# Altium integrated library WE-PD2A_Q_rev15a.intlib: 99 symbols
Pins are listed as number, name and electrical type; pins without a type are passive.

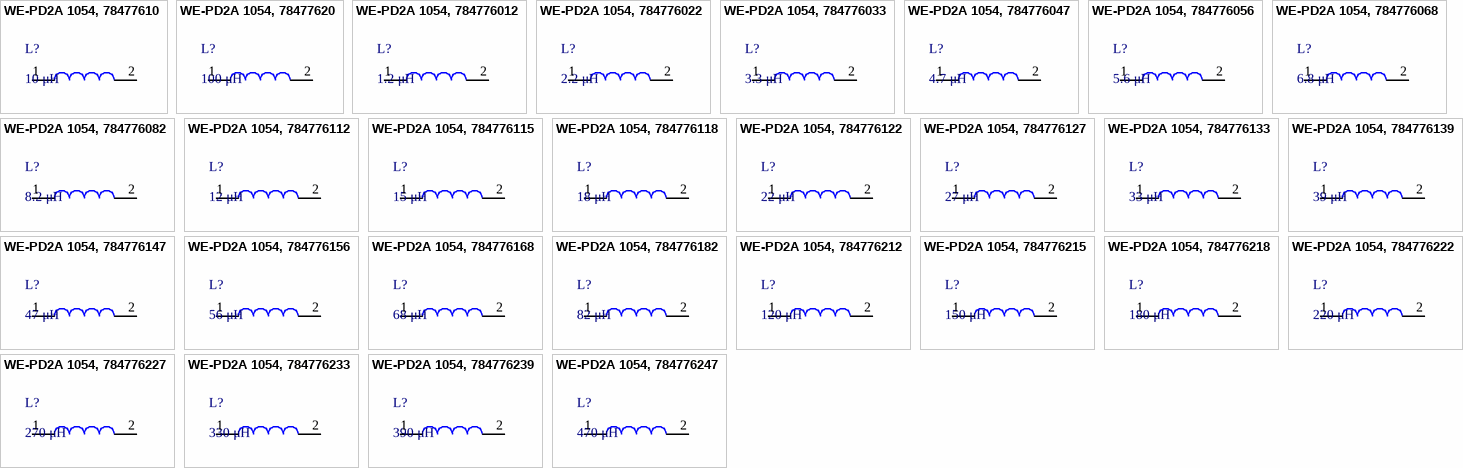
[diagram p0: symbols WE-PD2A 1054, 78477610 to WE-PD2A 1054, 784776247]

## WE-PD2A 1054, 78477610
designator L?, comment 10 μH
WE-PD2A SMD Power Inductor, Inductance = 10 μH; partNo: 78477610; Manufacturer: Wurth Elektronik
footprint WE-PD2A_1054
pins: 1, 2

## WE-PD2A 1054, 78477620
designator L?, comment 100 μH
WE-PD2A SMD Power Inductor, Inductance = 100 μH; partNo: 78477620; Manufacturer: Wurth Elektronik
footprint WE-PD2A_1054
pins: 1, 2

## WE-PD2A 1054, 784776012
designator L?, comment 1.2 μH
WE-PD2A SMD Power Inductor, Inductance = 1.2 μH; partNo: 784776012; Manufacturer: Wurth Elektronik
footprint WE-PD2A_1054
pins: 1, 2

## WE-PD2A 1054, 784776022
designator L?, comment 2.2 μH
WE-PD2A SMD Power Inductor, Inductance = 2.2 μH; partNo: 784776022; Manufacturer: Wurth Elektronik
footprint WE-PD2A_1054
pins: 1, 2

## WE-PD2A 1054, 784776033
designator L?, comment 3.3 μH
WE-PD2A SMD Power Inductor, Inductance = 3.3 μH; partNo: 784776033; Manufacturer: Wurth Elektronik
footprint WE-PD2A_1054
pins: 1, 2

## WE-PD2A 1054, 784776047
designator L?, comment 4.7 μH
WE-PD2A SMD Power Inductor, Inductance = 4.7 μH; partNo: 784776047; Manufacturer: Wurth Elektronik
footprint WE-PD2A_1054
pins: 1, 2

## WE-PD2A 1054, 784776056
designator L?, comment 5.6 μH
WE-PD2A SMD Power Inductor, Inductance = 5.6 μH; partNo: 784776056; Manufacturer: Wurth Elektronik
footprint WE-PD2A_1054
pins: 1, 2

## WE-PD2A 1054, 784776068
designator L?, comment 6.8 μH
WE-PD2A SMD Power Inductor, Inductance = 6.8 μH; partNo: 784776068; Manufacturer: Wurth Elektronik
footprint WE-PD2A_1054
pins: 1, 2

## WE-PD2A 1054, 784776082
designator L?, comment 8.2 μH
WE-PD2A SMD Power Inductor, Inductance = 8.2 μH; partNo: 784776082; Manufacturer: Wurth Elektronik
footprint WE-PD2A_1054
pins: 1, 2

## WE-PD2A 1054, 784776112
designator L?, comment 12 μH
WE-PD2A SMD Power Inductor, Inductance = 12 μH; partNo: 784776112; Manufacturer: Wurth Elektronik
footprint WE-PD2A_1054
pins: 1, 2

## WE-PD2A 1054, 784776115
designator L?, comment 15 μH
WE-PD2A SMD Power Inductor, Inductance = 15 μH; partNo: 784776115; Manufacturer: Wurth Elektronik
footprint WE-PD2A_1054
pins: 1, 2

## WE-PD2A 1054, 784776118
designator L?, comment 18 μH
WE-PD2A SMD Power Inductor, Inductance = 18 μH; partNo: 784776118; Manufacturer: Wurth Elektronik
footprint WE-PD2A_1054
pins: 1, 2

## WE-PD2A 1054, 784776122
designator L?, comment 22 μH
WE-PD2A SMD Power Inductor, Inductance = 22 μH; partNo: 784776122; Manufacturer: Wurth Elektronik
footprint WE-PD2A_1054
pins: 1, 2

## WE-PD2A 1054, 784776127
designator L?, comment 27 μH
WE-PD2A SMD Power Inductor, Inductance = 27 μH; partNo: 784776127; Manufacturer: Wurth Elektronik
footprint WE-PD2A_1054
pins: 1, 2

## WE-PD2A 1054, 784776133
designator L?, comment 33 μH
WE-PD2A SMD Power Inductor, Inductance = 33 μH; partNo: 784776133; Manufacturer: Wurth Elektronik
footprint WE-PD2A_1054
pins: 1, 2

## WE-PD2A 1054, 784776139
designator L?, comment 39 μH
WE-PD2A SMD Power Inductor, Inductance = 39 μH; partNo: 784776139; Manufacturer: Wurth Elektronik
footprint WE-PD2A_1054
pins: 1, 2

## WE-PD2A 1054, 784776147
designator L?, comment 47 μH
WE-PD2A SMD Power Inductor, Inductance = 47 μH; partNo: 784776147; Manufacturer: Wurth Elektronik
footprint WE-PD2A_1054
pins: 1, 2

## WE-PD2A 1054, 784776156
designator L?, comment 56 μH
WE-PD2A SMD Power Inductor, Inductance = 56 μH; partNo: 784776156; Manufacturer: Wurth Elektronik
footprint WE-PD2A_1054
pins: 1, 2

## WE-PD2A 1054, 784776168
designator L?, comment 68 μH
WE-PD2A SMD Power Inductor, Inductance = 68 μH; partNo: 784776168; Manufacturer: Wurth Elektronik
footprint WE-PD2A_1054
pins: 1, 2

## WE-PD2A 1054, 784776182
designator L?, comment 82 μH
WE-PD2A SMD Power Inductor, Inductance = 82 μH; partNo: 784776182; Manufacturer: Wurth Elektronik
footprint WE-PD2A_1054
pins: 1, 2

## WE-PD2A 1054, 784776212
designator L?, comment 120 μH
WE-PD2A SMD Power Inductor, Inductance = 120 μH; partNo: 784776212; Manufacturer: Wurth Elektronik
footprint WE-PD2A_1054
pins: 1, 2

## WE-PD2A 1054, 784776215
designator L?, comment 150 μH
WE-PD2A SMD Power Inductor, Inductance = 150 μH; partNo: 784776215; Manufacturer: Wurth Elektronik
footprint WE-PD2A_1054
pins: 1, 2

## WE-PD2A 1054, 784776218
designator L?, comment 180 μH
WE-PD2A SMD Power Inductor, Inductance = 180 μH; partNo: 784776218; Manufacturer: Wurth Elektronik
footprint WE-PD2A_1054
pins: 1, 2

## WE-PD2A 1054, 784776222
designator L?, comment 220 μH
WE-PD2A SMD Power Inductor, Inductance = 220 μH; partNo: 784776222; Manufacturer: Wurth Elektronik
footprint WE-PD2A_1054
pins: 1, 2

## WE-PD2A 1054, 784776227
designator L?, comment 270 μH
WE-PD2A SMD Power Inductor, Inductance = 270 μH; partNo: 784776227; Manufacturer: Wurth Elektronik
footprint WE-PD2A_1054
pins: 1, 2

## WE-PD2A 1054, 784776233
designator L?, comment 330 μH
WE-PD2A SMD Power Inductor, Inductance = 330 μH; partNo: 784776233; Manufacturer: Wurth Elektronik
footprint WE-PD2A_1054
pins: 1, 2

## WE-PD2A 1054, 784776239
designator L?, comment 390 μH
WE-PD2A SMD Power Inductor, Inductance = 390 μH; partNo: 784776239; Manufacturer: Wurth Elektronik
footprint WE-PD2A_1054
pins: 1, 2

## WE-PD2A 1054, 784776247
designator L?, comment 470 μH
WE-PD2A SMD Power Inductor, Inductance = 470 μH; partNo: 784776247; Manufacturer: Wurth Elektronik
footprint WE-PD2A_1054
pins: 1, 2


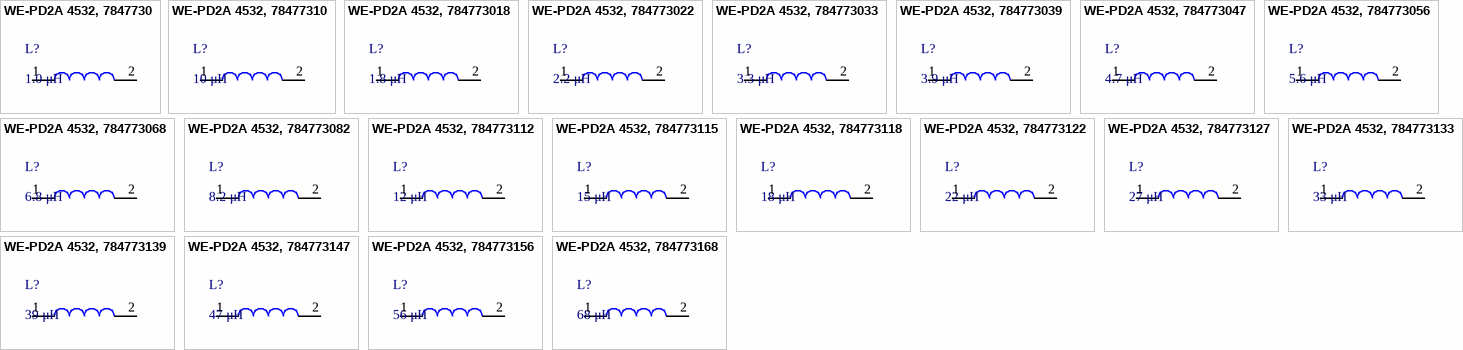
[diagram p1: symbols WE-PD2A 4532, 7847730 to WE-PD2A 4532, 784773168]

## WE-PD2A 4532, 7847730
designator L?, comment 1.0 μH
WE-PD2A SMD Power Inductor, Inductance = 1.0 μH; partNo: 7847730; Manufacturer: Wurth Elektronik
footprint WE-PD2A_4532
pins: 1, 2

## WE-PD2A 4532, 78477310
designator L?, comment 10 μH
WE-PD2A SMD Power Inductor, Inductance = 10 μH; partNo: 78477310; Manufacturer: Wurth Elektronik
footprint WE-PD2A_4532
pins: 1, 2

## WE-PD2A 4532, 784773018
designator L?, comment 1.8 μH
WE-PD2A SMD Power Inductor, Inductance = 1.8 μH; partNo: 784773018; Manufacturer: Wurth Elektronik
footprint WE-PD2A_4532
pins: 1, 2

## WE-PD2A 4532, 784773022
designator L?, comment 2.2 μH
WE-PD2A SMD Power Inductor, Inductance = 2.2 μH; partNo: 784773022; Manufacturer: Wurth Elektronik
footprint WE-PD2A_4532
pins: 1, 2

## WE-PD2A 4532, 784773033
designator L?, comment 3.3 μH
WE-PD2A SMD Power Inductor, Inductance = 3.3 μH; partNo: 784773033; Manufacturer: Wurth Elektronik
footprint WE-PD2A_4532
pins: 1, 2

## WE-PD2A 4532, 784773039
designator L?, comment 3.9 μH
WE-PD2A SMD Power Inductor, Inductance = 3.9 μH; partNo: 784773039; Manufacturer: Wurth Elektronik
footprint WE-PD2A_4532
pins: 1, 2

## WE-PD2A 4532, 784773047
designator L?, comment 4.7 μH
WE-PD2A SMD Power Inductor, Inductance = 4.7 μH; partNo: 784773047; Manufacturer: Wurth Elektronik
footprint WE-PD2A_4532
pins: 1, 2

## WE-PD2A 4532, 784773056
designator L?, comment 5.6 μH
WE-PD2A SMD Power Inductor, Inductance = 5.6 μH; partNo: 784773056; Manufacturer: Wurth Elektronik
footprint WE-PD2A_4532
pins: 1, 2

## WE-PD2A 4532, 784773068
designator L?, comment 6.8 μH
WE-PD2A SMD Power Inductor, Inductance = 6.8 μH; partNo: 784773068; Manufacturer: Wurth Elektronik
footprint WE-PD2A_4532
pins: 1, 2

## WE-PD2A 4532, 784773082
designator L?, comment 8.2 μH
WE-PD2A SMD Power Inductor, Inductance = 8.2 μH; partNo: 784773082; Manufacturer: Wurth Elektronik
footprint WE-PD2A_4532
pins: 1, 2

## WE-PD2A 4532, 784773112
designator L?, comment 12 μH
WE-PD2A SMD Power Inductor, Inductance = 12 μH; partNo: 784773112; Manufacturer: Wurth Elektronik
footprint WE-PD2A_4532
pins: 1, 2

## WE-PD2A 4532, 784773115
designator L?, comment 15 μH
WE-PD2A SMD Power Inductor, Inductance = 15 μH; partNo: 784773115; Manufacturer: Wurth Elektronik
footprint WE-PD2A_4532
pins: 1, 2

## WE-PD2A 4532, 784773118
designator L?, comment 18 μH
WE-PD2A SMD Power Inductor, Inductance = 18 μH; partNo: 784773118; Manufacturer: Wurth Elektronik
footprint WE-PD2A_4532
pins: 1, 2

## WE-PD2A 4532, 784773122
designator L?, comment 22 μH
WE-PD2A SMD Power Inductor, Inductance = 22 μH; partNo: 784773122; Manufacturer: Wurth Elektronik
footprint WE-PD2A_4532
pins: 1, 2

## WE-PD2A 4532, 784773127
designator L?, comment 27 μH
WE-PD2A SMD Power Inductor, Inductance = 27 μH; partNo: 784773127; Manufacturer: Wurth Elektronik
footprint WE-PD2A_4532
pins: 1, 2

## WE-PD2A 4532, 784773133
designator L?, comment 33 μH
WE-PD2A SMD Power Inductor, Inductance = 33 μH; partNo: 784773133; Manufacturer: Wurth Elektronik
footprint WE-PD2A_4532
pins: 1, 2

## WE-PD2A 4532, 784773139
designator L?, comment 39 μH
WE-PD2A SMD Power Inductor, Inductance = 39 μH; partNo: 784773139; Manufacturer: Wurth Elektronik
footprint WE-PD2A_4532
pins: 1, 2

## WE-PD2A 4532, 784773147
designator L?, comment 47 μH
WE-PD2A SMD Power Inductor, Inductance = 47 μH; partNo: 784773147; Manufacturer: Wurth Elektronik
footprint WE-PD2A_4532
pins: 1, 2

## WE-PD2A 4532, 784773156
designator L?, comment 56 μH
WE-PD2A SMD Power Inductor, Inductance = 56 μH; partNo: 784773156; Manufacturer: Wurth Elektronik
footprint WE-PD2A_4532
pins: 1, 2

## WE-PD2A 4532, 784773168
designator L?, comment 68 μH
WE-PD2A SMD Power Inductor, Inductance = 68 μH; partNo: 784773168; Manufacturer: Wurth Elektronik
footprint WE-PD2A_4532
pins: 1, 2


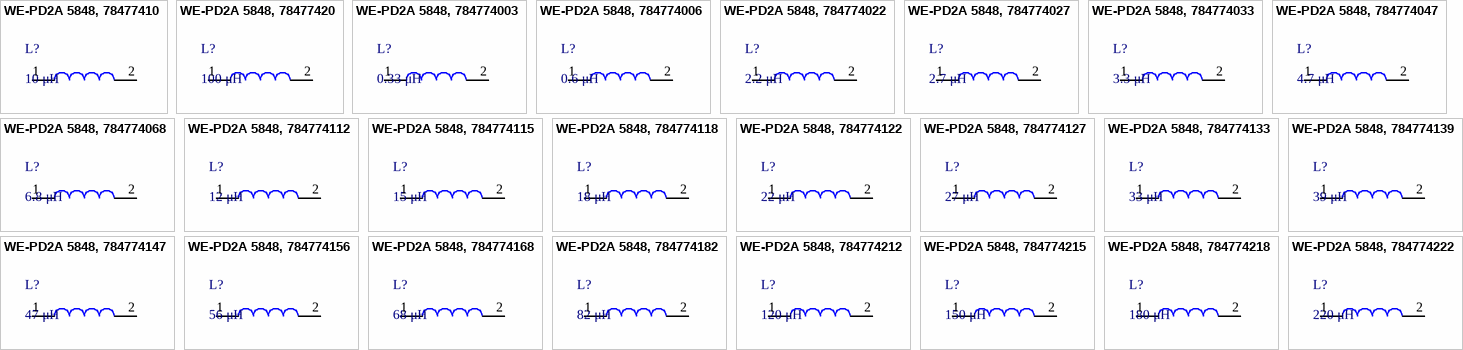
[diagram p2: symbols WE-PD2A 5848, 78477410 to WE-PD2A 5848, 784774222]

## WE-PD2A 5848, 78477410
designator L?, comment 10 μH
WE-PD2A SMD Power Inductor, Inductance = 10 μH; partNo: 78477410; Manufacturer: Wurth Elektronik
footprint WE-PD2A_5848
pins: 1, 2

## WE-PD2A 5848, 78477420
designator L?, comment 100 μH
WE-PD2A SMD Power Inductor, Inductance = 100 μH; partNo: 78477420; Manufacturer: Wurth Elektronik
footprint WE-PD2A_5848
pins: 1, 2

## WE-PD2A 5848, 784774003
designator L?, comment 0.33 μH
WE-PD2A SMD Power Inductor, Inductance = 0.33 μH; partNo: 784774003; Manufacturer: Wurth Elektronik
footprint WE-PD2A_5848
pins: 1, 2

## WE-PD2A 5848, 784774006
designator L?, comment 0.6 μH
WE-PD2A SMD Power Inductor, Inductance = 0.6 μH; partNo: 784774006; Manufacturer: Wurth Elektronik
footprint WE-PD2A_5848
pins: 1, 2

## WE-PD2A 5848, 784774022
designator L?, comment 2.2 μH
WE-PD2A SMD Power Inductor, Inductance = 2.2 μH; partNo: 784774022; Manufacturer: Wurth Elektronik
footprint WE-PD2A_5848
pins: 1, 2

## WE-PD2A 5848, 784774027
designator L?, comment 2.7 μH
WE-PD2A SMD Power Inductor, Inductance = 2.7 μH; partNo: 784774027; Manufacturer: Wurth Elektronik
footprint WE-PD2A_5848
pins: 1, 2

## WE-PD2A 5848, 784774033
designator L?, comment 3.3 μH
WE-PD2A SMD Power Inductor, Inductance = 3.3 μH; partNo: 784774033; Manufacturer: Wurth Elektronik
footprint WE-PD2A_5848
pins: 1, 2

## WE-PD2A 5848, 784774047
designator L?, comment 4.7 μH
WE-PD2A SMD Power Inductor, Inductance = 4.7 μH; partNo: 784774047; Manufacturer: Wurth Elektronik
footprint WE-PD2A_5848
pins: 1, 2

## WE-PD2A 5848, 784774068
designator L?, comment 6.8 μH
WE-PD2A SMD Power Inductor, Inductance = 6.8 μH; partNo: 784774068; Manufacturer: Wurth Elektronik
footprint WE-PD2A_5848
pins: 1, 2

## WE-PD2A 5848, 784774112
designator L?, comment 12 μH
WE-PD2A SMD Power Inductor, Inductance = 12 μH; partNo: 784774112; Manufacturer: Wurth Elektronik
footprint WE-PD2A_5848
pins: 1, 2

## WE-PD2A 5848, 784774115
designator L?, comment 15 μH
WE-PD2A SMD Power Inductor, Inductance = 15 μH; partNo: 784774115; Manufacturer: Wurth Elektronik
footprint WE-PD2A_5848
pins: 1, 2

## WE-PD2A 5848, 784774118
designator L?, comment 18 μH
WE-PD2A SMD Power Inductor, Inductance = 18 μH; partNo: 784774118; Manufacturer: Wurth Elektronik
footprint WE-PD2A_5848
pins: 1, 2

## WE-PD2A 5848, 784774122
designator L?, comment 22 μH
WE-PD2A SMD Power Inductor, Inductance = 22 μH; partNo: 784774122; Manufacturer: Wurth Elektronik
footprint WE-PD2A_5848
pins: 1, 2

## WE-PD2A 5848, 784774127
designator L?, comment 27 μH
WE-PD2A SMD Power Inductor, Inductance = 27 μH; partNo: 784774127; Manufacturer: Wurth Elektronik
footprint WE-PD2A_5848
pins: 1, 2

## WE-PD2A 5848, 784774133
designator L?, comment 33 μH
WE-PD2A SMD Power Inductor, Inductance = 33 μH; partNo: 784774133; Manufacturer: Wurth Elektronik
footprint WE-PD2A_5848
pins: 1, 2

## WE-PD2A 5848, 784774139
designator L?, comment 39 μH
WE-PD2A SMD Power Inductor, Inductance = 39 μH; partNo: 784774139; Manufacturer: Wurth Elektronik
footprint WE-PD2A_5848
pins: 1, 2

## WE-PD2A 5848, 784774147
designator L?, comment 47 μH
WE-PD2A SMD Power Inductor, Inductance = 47 μH; partNo: 784774147; Manufacturer: Wurth Elektronik
footprint WE-PD2A_5848
pins: 1, 2

## WE-PD2A 5848, 784774156
designator L?, comment 56 μH
WE-PD2A SMD Power Inductor, Inductance = 56 μH; partNo: 784774156; Manufacturer: Wurth Elektronik
footprint WE-PD2A_5848
pins: 1, 2

## WE-PD2A 5848, 784774168
designator L?, comment 68 μH
WE-PD2A SMD Power Inductor, Inductance = 68 μH; partNo: 784774168; Manufacturer: Wurth Elektronik
footprint WE-PD2A_5848
pins: 1, 2

## WE-PD2A 5848, 784774182
designator L?, comment 82 μH
WE-PD2A SMD Power Inductor, Inductance = 82 μH; partNo: 784774182; Manufacturer: Wurth Elektronik
footprint WE-PD2A_5848
pins: 1, 2

## WE-PD2A 5848, 784774212
designator L?, comment 120 μH
WE-PD2A SMD Power Inductor, Inductance = 120 μH; partNo: 784774212; Manufacturer: Wurth Elektronik
footprint WE-PD2A_5848
pins: 1, 2

## WE-PD2A 5848, 784774215
designator L?, comment 150 μH
WE-PD2A SMD Power Inductor, Inductance = 150 μH; partNo: 784774215; Manufacturer: Wurth Elektronik
footprint WE-PD2A_5848
pins: 1, 2

## WE-PD2A 5848, 784774218
designator L?, comment 180 μH
WE-PD2A SMD Power Inductor, Inductance = 180 μH; partNo: 784774218; Manufacturer: Wurth Elektronik
footprint WE-PD2A_5848
pins: 1, 2

## WE-PD2A 5848, 784774222
designator L?, comment 220 μH
WE-PD2A SMD Power Inductor, Inductance = 220 μH; partNo: 784774222; Manufacturer: Wurth Elektronik
footprint WE-PD2A_5848
pins: 1, 2


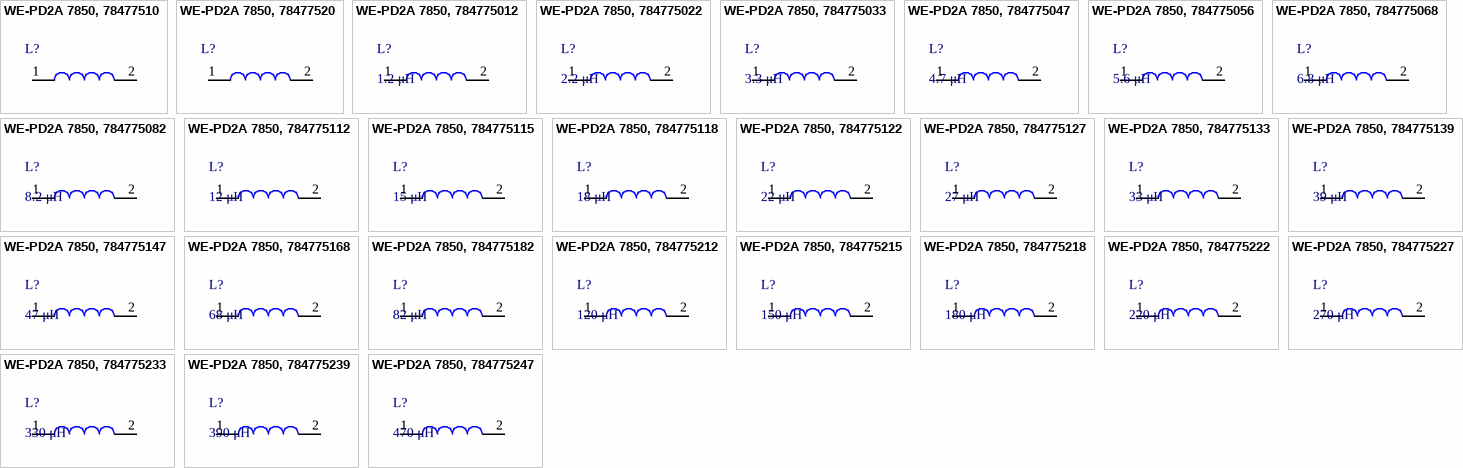
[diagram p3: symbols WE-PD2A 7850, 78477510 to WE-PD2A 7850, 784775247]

## WE-PD2A 7850, 78477510
designator L?
WE-PD2A SMD Power Inductor, Inductance = 10 μH; Manufacturer: Wurth Elektronik
footprint WE-PD2A_7850
pins: 1, 2

## WE-PD2A 7850, 78477520
designator L?
WE-PD2A SMD Power Inductor, Inductance = 100 μH; Manufacturer: Wurth Elektronik
footprint WE-PD2A_7850
pins: 1, 2

## WE-PD2A 7850, 784775012
designator L?, comment 1.2 μH
WE-PD2A SMD Power Inductor, Inductance = 1.2 μH; partNo: 784775012; Manufacturer: Wurth Elektronik
footprint WE-PD2A_7850
pins: 1, 2

## WE-PD2A 7850, 784775022
designator L?, comment 2.2 μH
WE-PD2A SMD Power Inductor, Inductance = 2.2 μH; partNo: 784775022; Manufacturer: Wurth Elektronik
footprint WE-PD2A_7850
pins: 1, 2

## WE-PD2A 7850, 784775033
designator L?, comment 3.3 μH
WE-PD2A SMD Power Inductor, Inductance = 3.3 μH; partNo: 784775033; Manufacturer: Wurth Elektronik
footprint WE-PD2A_7850
pins: 1, 2

## WE-PD2A 7850, 784775047
designator L?, comment 4.7 μH
WE-PD2A SMD Power Inductor, Inductance = 4.7 μH; partNo: 784775047; Manufacturer: Wurth Elektronik
footprint WE-PD2A_7850
pins: 1, 2

## WE-PD2A 7850, 784775056
designator L?, comment 5.6 μH
WE-PD2A SMD Power Inductor, Inductance = 5.6 μH; partNo: 784775056; Manufacturer: Wurth Elektronik
footprint WE-PD2A_7850
pins: 1, 2

## WE-PD2A 7850, 784775068
designator L?, comment 6.8 μH
WE-PD2A SMD Power Inductor, Inductance = 6.8 μH; partNo: 784775068; Manufacturer: Wurth Elektronik
footprint WE-PD2A_7850
pins: 1, 2

## WE-PD2A 7850, 784775082
designator L?, comment 8.2 μH
WE-PD2A SMD Power Inductor, Inductance = 8.2 μH; partNo: 784775082; Manufacturer: Wurth Elektronik
footprint WE-PD2A_7850
pins: 1, 2

## WE-PD2A 7850, 784775112
designator L?, comment 12 μH
WE-PD2A SMD Power Inductor, Inductance = 12 μH; partNo: 784775112; Manufacturer: Wurth Elektronik
footprint WE-PD2A_7850
pins: 1, 2

## WE-PD2A 7850, 784775115
designator L?, comment 15 μH
WE-PD2A SMD Power Inductor, Inductance = 15 μH; partNo: 784775115; Manufacturer: Wurth Elektronik
footprint WE-PD2A_7850
pins: 1, 2

## WE-PD2A 7850, 784775118
designator L?, comment 18 μH
WE-PD2A SMD Power Inductor, Inductance = 18 μH; partNo: 784775118; Manufacturer: Wurth Elektronik
footprint WE-PD2A_7850
pins: 1, 2

## WE-PD2A 7850, 784775122
designator L?, comment 22 μH
WE-PD2A SMD Power Inductor, Inductance = 22 μH; partNo: 784775122; Manufacturer: Wurth Elektronik
footprint WE-PD2A_7850
pins: 1, 2

## WE-PD2A 7850, 784775127
designator L?, comment 27 μH
WE-PD2A SMD Power Inductor, Inductance = 27 μH; partNo: 784775127; Manufacturer: Wurth Elektronik
footprint WE-PD2A_7850
pins: 1, 2

## WE-PD2A 7850, 784775133
designator L?, comment 33 μH
WE-PD2A SMD Power Inductor, Inductance = 33 μH; partNo: 784775133; Manufacturer: Wurth Elektronik
footprint WE-PD2A_7850
pins: 1, 2

## WE-PD2A 7850, 784775139
designator L?, comment 39 μH
WE-PD2A SMD Power Inductor, Inductance = 39 μH; partNo: 784775139; Manufacturer: Wurth Elektronik
footprint WE-PD2A_7850
pins: 1, 2

## WE-PD2A 7850, 784775147
designator L?, comment 47 μH
WE-PD2A SMD Power Inductor, Inductance = 47 μH; partNo: 784775147; Manufacturer: Wurth Elektronik
footprint WE-PD2A_7850
pins: 1, 2

## WE-PD2A 7850, 784775168
designator L?, comment 68 μH
WE-PD2A SMD Power Inductor, Inductance = 68 μH; partNo: 784775168; Manufacturer: Wurth Elektronik
footprint WE-PD2A_7850
pins: 1, 2

## WE-PD2A 7850, 784775182
designator L?, comment 82 μH
WE-PD2A SMD Power Inductor, Inductance = 82 μH; partNo: 784775182; Manufacturer: Wurth Elektronik
footprint WE-PD2A_7850
pins: 1, 2

## WE-PD2A 7850, 784775212
designator L?, comment 120 μH
WE-PD2A SMD Power Inductor, Inductance = 120 μH; partNo: 784775212; Manufacturer: Wurth Elektronik
footprint WE-PD2A_7850
pins: 1, 2

## WE-PD2A 7850, 784775215
designator L?, comment 150 μH
WE-PD2A SMD Power Inductor, Inductance = 150 μH; partNo: 784775215; Manufacturer: Wurth Elektronik
footprint WE-PD2A_7850
pins: 1, 2

## WE-PD2A 7850, 784775218
designator L?, comment 180 μH
WE-PD2A SMD Power Inductor, Inductance = 180 μH; partNo: 784775218; Manufacturer: Wurth Elektronik
footprint WE-PD2A_7850
pins: 1, 2

## WE-PD2A 7850, 784775222
designator L?, comment 220 μH
WE-PD2A SMD Power Inductor, Inductance = 220 μH; partNo: 784775222; Manufacturer: Wurth Elektronik
footprint WE-PD2A_7850
pins: 1, 2

## WE-PD2A 7850, 784775227
designator L?, comment 270 μH
WE-PD2A SMD Power Inductor, Inductance = 270 μH; partNo: 784775227; Manufacturer: Wurth Elektronik
footprint WE-PD2A_7850
pins: 1, 2

## WE-PD2A 7850, 784775233
designator L?, comment 330 μH
WE-PD2A SMD Power Inductor, Inductance = 330 μH; partNo: 784775233; Manufacturer: Wurth Elektronik
footprint WE-PD2A_7850
pins: 1, 2

## WE-PD2A 7850, 784775239
designator L?, comment 390 μH
WE-PD2A SMD Power Inductor, Inductance = 390 μH; partNo: 784775239; Manufacturer: Wurth Elektronik
footprint WE-PD2A_7850
pins: 1, 2

## WE-PD2A 7850, 784775247
designator L?, comment 470 μH
WE-PD2A SMD Power Inductor, Inductance = 470 μH; partNo: 784775247; Manufacturer: Wurth Elektronik
footprint WE-PD2A_7850
pins: 1, 2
